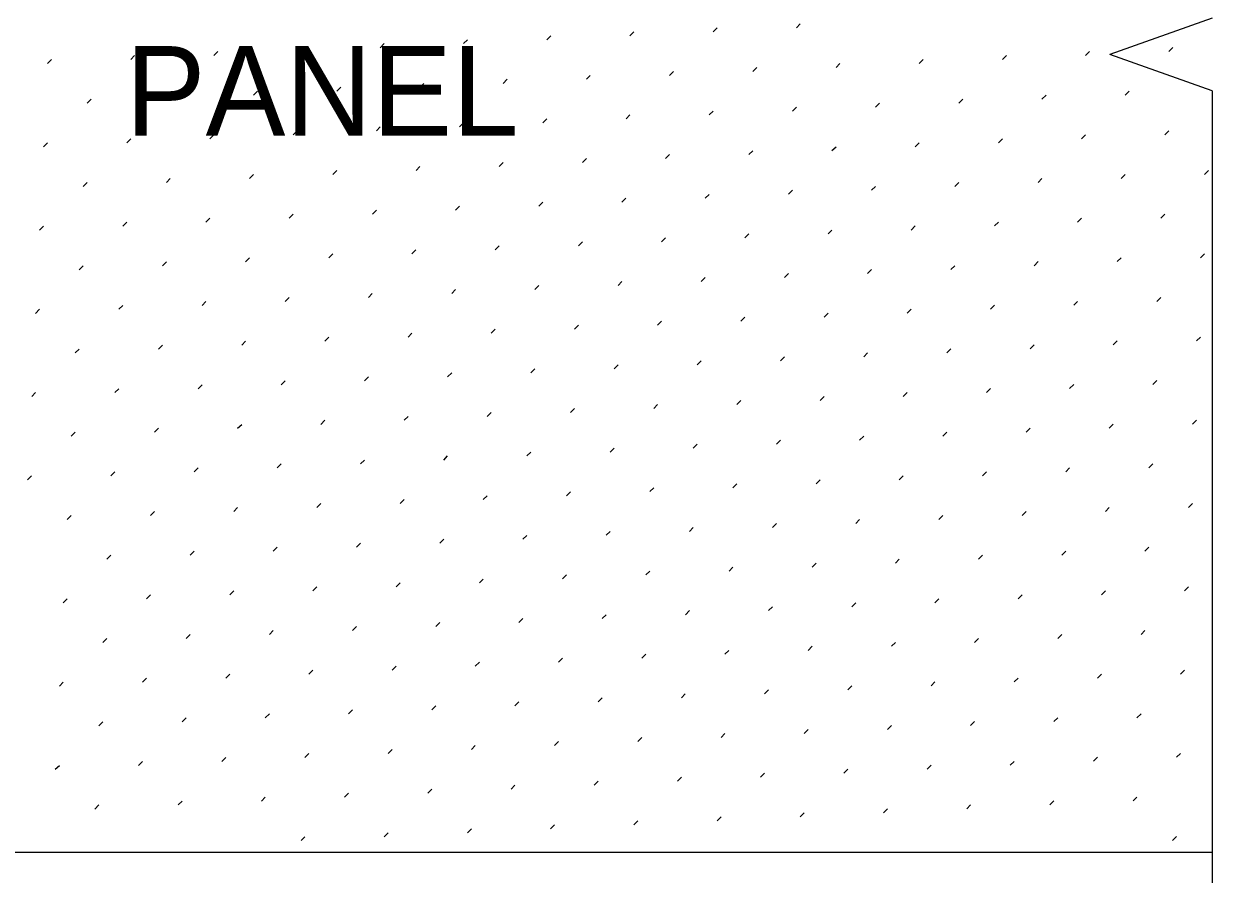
# Model space of a CAD drawing. Extents: x 49991.4 to 50021, y 49987.6 to 50011.4.
# Drawn here: x 50014.07 to 50015.13, y 49996.272 to 49997.03 of the extents above; entities that cross this region are included whole.
import ezdxf

# ---------------------------------------------------------------- set-up
doc = ezdxf.new("R2010")
doc.units = 0
for name, color, linetype in [('Level 1', 7, 'Continuous'), ('Level 10', 7, 'Continuous'), ('Level 2', 7, 'Continuous'), ('Level 6', 7, 'Continuous')]:
    doc.layers.add(name, color=color, linetype=linetype)

msp = doc.modelspace()

# ---------------------------------------------------------------- linework, layer by layer
at = {"layer": 'Level 1'}
msp.add_line((50013.9348, 49996.2915), (50015.1301, 49996.2915), dxfattribs=at)
at = {"layer": 'Level 10'}
for p, q in [((50014.6105, 49997.0196), (50014.614, 49997.0231)), ((50014.6848, 49997.0231), (50014.6883, 49997.0267)), ((50014.759, 49997.0267), (50014.7625, 49997.0302)), ((50014.3877, 49997.0089), (50014.3913, 49997.0125)), ((50014.462, 49997.0125), (50014.4655, 49997.016)), ((50014.5362, 49997.016), (50014.5398, 49997.0196)), ((50014.165, 49996.9983), (50014.1685, 49997.0019)), ((50014.2392, 49997.0019), (50014.2428, 49997.0054)), ((50014.3135, 49997.0054), (50014.317, 49997.0089)), ((50014.9429, 49996.9984), (50014.9464, 49997.0019)), ((50015.0171, 49997.0019), (50015.0207, 49997.0055)), ((50015.0914, 49997.0055), (50015.0949, 49997.009)), ((50014.0907, 49996.9948), (50014.0943, 49996.9983)), ((50014.7201, 49996.9878), (50014.7236, 49996.9913)), ((50014.7944, 49996.9913), (50014.7979, 49996.9948)), ((50014.8686, 49996.9948), (50014.8721, 49996.9984)), ((50014.4973, 49996.9771), (50014.5009, 49996.9807)), ((50014.5716, 49996.9807), (50014.5751, 49996.9842)), ((50014.6459, 49996.9842), (50014.6494, 49996.9878)), ((50014.2746, 49996.9665), (50014.2781, 49996.97)), ((50014.3488, 49996.97), (50014.3524, 49996.9736)), ((50014.4231, 49996.9736), (50014.4266, 49996.9771)), ((50015.0525, 49996.9666), (50015.056, 49996.9701)), ((50014.1261, 49996.9594), (50014.1296, 49996.963)), ((50014.2003, 49996.963), (50014.2039, 49996.9665)), ((50014.8297, 49996.9559), (50014.8333, 49996.9595)), ((50014.904, 49996.9595), (50014.9075, 49996.963)), ((50014.9782, 49996.963), (50014.9818, 49996.9666)), ((50014.607, 49996.9453), (50014.6105, 49996.9489)), ((50014.6812, 49996.9489), (50014.6847, 49996.9524)), ((50014.7555, 49996.9524), (50014.759, 49996.9559)), ((50014.3842, 49996.9347), (50014.3877, 49996.9382)), ((50014.4584, 49996.9382), (50014.462, 49996.9418)), ((50014.5327, 49996.9418), (50014.5362, 49996.9453)), ((50014.1614, 49996.9241), (50014.165, 49996.9276)), ((50014.2357, 49996.9276), (50014.2392, 49996.9311)), ((50014.3099, 49996.9312), (50014.3135, 49996.9347)), ((50014.9393, 49996.9241), (50014.9429, 49996.9277)), ((50015.0136, 49996.9277), (50015.0171, 49996.9312)), ((50015.0878, 49996.9312), (50015.0914, 49996.9348)), ((50014.0872, 49996.9205), (50014.0907, 49996.9241)), ((50014.7166, 49996.9135), (50014.7201, 49996.917)), ((50014.7908, 49996.9171), (50014.7944, 49996.9206)), ((50014.8651, 49996.9206), (50014.8686, 49996.9241)), ((50014.4938, 49996.9029), (50014.4973, 49996.9064)), ((50014.5681, 49996.9064), (50014.5716, 49996.91)), ((50014.6423, 49996.91), (50014.6458, 49996.9135)), ((50014.271, 49996.8923), (50014.2746, 49996.8958)), ((50014.3453, 49996.8958), (50014.3488, 49996.8993)), ((50014.4196, 49996.8993), (50014.4231, 49996.9029)), ((50015.0489, 49996.8923), (50015.0525, 49996.8959)), ((50015.1232, 49996.8959), (50015.1267, 49996.8994)), ((50014.1225, 49996.8852), (50014.1261, 49996.8887)), ((50014.1968, 49996.8887), (50014.2003, 49996.8922)), ((50014.8262, 49996.8817), (50014.8297, 49996.8852)), ((50014.9004, 49996.8852), (50014.904, 49996.8888)), ((50014.9747, 49996.8888), (50014.9782, 49996.8923)), ((50014.6034, 49996.8711), (50014.6069, 49996.8746)), ((50014.6777, 49996.8746), (50014.6812, 49996.8781)), ((50014.7519, 49996.8782), (50014.7555, 49996.8817)), ((50014.3807, 49996.8604), (50014.3842, 49996.864)), ((50014.4549, 49996.864), (50014.4584, 49996.8675)), ((50014.5292, 49996.8675), (50014.5327, 49996.8711)), ((50014.1579, 49996.8498), (50014.1614, 49996.8533)), ((50014.2321, 49996.8534), (50014.2357, 49996.8569)), ((50014.3064, 49996.8569), (50014.3099, 49996.8604)), ((50014.9358, 49996.8499), (50014.9393, 49996.8534)), ((50015.01, 49996.8534), (50015.0136, 49996.857)), ((50015.0843, 49996.857), (50015.0878, 49996.8605)), ((50014.0836, 49996.8463), (50014.0872, 49996.8498)), ((50014.713, 49996.8393), (50014.7166, 49996.8428)), ((50014.7873, 49996.8428), (50014.7908, 49996.8463)), ((50014.8615, 49996.8463), (50014.8651, 49996.8499)), ((50014.4903, 49996.8286), (50014.4938, 49996.8322)), ((50014.5645, 49996.8322), (50014.5681, 49996.8357)), ((50014.6388, 49996.8357), (50014.6423, 49996.8392)), ((50014.2675, 49996.818), (50014.271, 49996.8215)), ((50014.3418, 49996.8215), (50014.3453, 49996.8251)), ((50014.416, 49996.8251), (50014.4195, 49996.8286)), ((50015.0454, 49996.8181), (50015.0489, 49996.8216)), ((50015.1196, 49996.8216), (50015.1232, 49996.8251)), ((50014.119, 49996.8109), (50014.1225, 49996.8144)), ((50014.1932, 49996.8145), (50014.1968, 49996.818)), ((50014.8226, 49996.8074), (50014.8262, 49996.811)), ((50014.8969, 49996.811), (50014.9004, 49996.8145)), ((50014.9711, 49996.8145), (50014.9747, 49996.8181)), ((50014.5999, 49996.7968), (50014.6034, 49996.8003)), ((50014.6741, 49996.8004), (50014.6777, 49996.8039)), ((50014.7484, 49996.8039), (50014.7519, 49996.8074)), ((50014.3771, 49996.7862), (50014.3806, 49996.7897)), ((50014.4514, 49996.7897), (50014.4549, 49996.7933)), ((50014.5256, 49996.7933), (50014.5292, 49996.7968)), ((50014.1544, 49996.7756), (50014.1579, 49996.7791)), ((50014.2286, 49996.7791), (50014.2321, 49996.7826)), ((50014.3029, 49996.7826), (50014.3064, 49996.7862)), ((50014.9322, 49996.7756), (50014.9358, 49996.7792)), ((50015.0065, 49996.7792), (50015.01, 49996.7827)), ((50015.0807, 49996.7827), (50015.0843, 49996.7862)), ((50014.0801, 49996.772), (50014.0836, 49996.7756)), ((50014.7095, 49996.765), (50014.713, 49996.7685)), ((50014.7837, 49996.7685), (50014.7873, 49996.7721)), ((50014.858, 49996.7721), (50014.8615, 49996.7756)), ((50014.4867, 49996.7544), (50014.4903, 49996.7579)), ((50014.561, 49996.7579), (50014.5645, 49996.7615)), ((50014.6352, 49996.7615), (50014.6388, 49996.765)), ((50014.264, 49996.7437), (50014.2675, 49996.7473)), ((50014.3382, 49996.7473), (50014.3417, 49996.7508)), ((50014.4125, 49996.7508), (50014.416, 49996.7544)), ((50015.0418, 49996.7438), (50015.0454, 49996.7474)), ((50015.1161, 49996.7474), (50015.1196, 49996.7509)), ((50014.1155, 49996.7367), (50014.119, 49996.7402)), ((50014.1897, 49996.7402), (50014.1932, 49996.7437)), ((50014.8191, 49996.7332), (50014.8226, 49996.7367)), ((50014.8933, 49996.7367), (50014.8969, 49996.7403)), ((50014.9676, 49996.7403), (50014.9711, 49996.7438)), ((50014.5963, 49996.7226), (50014.5999, 49996.7261)), ((50014.6706, 49996.7261), (50014.6741, 49996.7296)), ((50014.7448, 49996.7296), (50014.7484, 49996.7332)), ((50014.3736, 49996.7119), (50014.3771, 49996.7155)), ((50014.4478, 49996.7155), (50014.4514, 49996.719)), ((50014.5221, 49996.719), (50014.5256, 49996.7226)), ((50014.1508, 49996.7013), (50014.1543, 49996.7048)), ((50014.2251, 49996.7048), (50014.2286, 49996.7084)), ((50014.2993, 49996.7084), (50014.3028, 49996.7119)), ((50014.9287, 49996.7014), (50014.9322, 49996.7049)), ((50015.0029, 49996.7049), (50015.0065, 49996.7085)), ((50015.0772, 49996.7085), (50015.0807, 49996.712)), ((50014.0766, 49996.6978), (50014.0801, 49996.7013)), ((50014.7059, 49996.6907), (50014.7095, 49996.6943)), ((50014.7802, 49996.6943), (50014.7837, 49996.6978)), ((50014.8544, 49996.6978), (50014.858, 49996.7014)), ((50014.4832, 49996.6801), (50014.4867, 49996.6837)), ((50014.5574, 49996.6837), (50014.561, 49996.6872)), ((50014.6317, 49996.6872), (50014.6352, 49996.6907)), ((50014.2604, 49996.6695), (50014.264, 49996.673)), ((50014.3347, 49996.673), (50014.3382, 49996.6766)), ((50014.4089, 49996.6766), (50014.4125, 49996.6801)), ((50015.0383, 49996.6696), (50015.0418, 49996.6731)), ((50015.1126, 49996.6731), (50015.1161, 49996.6766)), ((50014.1119, 49996.6624), (50014.1154, 49996.6659)), ((50014.1862, 49996.6659), (50014.1897, 49996.6695)), ((50014.8155, 49996.6589), (50014.8191, 49996.6625)), ((50014.8898, 49996.6625), (50014.8933, 49996.666)), ((50014.9641, 49996.666), (50014.9676, 49996.6696)), ((50014.5928, 49996.6483), (50014.5963, 49996.6518)), ((50014.667, 49996.6519), (50014.6706, 49996.6554)), ((50014.7413, 49996.6554), (50014.7448, 49996.6589)), ((50014.37, 49996.6377), (50014.3736, 49996.6412)), ((50014.4443, 49996.6412), (50014.4478, 49996.6448)), ((50014.5185, 49996.6448), (50014.5221, 49996.6483)), ((50014.1473, 49996.6271), (50014.1508, 49996.6306)), ((50014.2215, 49996.6306), (50014.2251, 49996.6341)), ((50014.2958, 49996.6341), (50014.2993, 49996.6377)), ((50014.9252, 49996.6271), (50014.9287, 49996.6307)), ((50014.9994, 49996.6307), (50015.0029, 49996.6342)), ((50015.0737, 49996.6342), (50015.0772, 49996.6377)), ((50014.073, 49996.6235), (50014.0765, 49996.627)), ((50014.7024, 49996.6165), (50014.7059, 49996.62)), ((50014.7766, 49996.62), (50014.7802, 49996.6236)), ((50014.8509, 49996.6236), (50014.8544, 49996.6271)), ((50014.4796, 49996.6059), (50014.4832, 49996.6094)), ((50014.5539, 49996.6094), (50014.5574, 49996.6129)), ((50014.6281, 49996.613), (50014.6317, 49996.6165)), ((50014.2569, 49996.5952), (50014.2604, 49996.5988)), ((50014.3311, 49996.5988), (50014.3347, 49996.6023)), ((50014.4054, 49996.6023), (50014.4089, 49996.6059)), ((50015.0348, 49996.5953), (50015.0383, 49996.5988)), ((50015.109, 49996.5989), (50015.1126, 49996.6024)), ((50014.1084, 49996.5882), (50014.1119, 49996.5917)), ((50014.1826, 49996.5917), (50014.1862, 49996.5952)), ((50014.812, 49996.5847), (50014.8155, 49996.5882)), ((50014.8863, 49996.5882), (50014.8898, 49996.5918)), ((50014.9605, 49996.5918), (50014.964, 49996.5953)), ((50014.5892, 49996.5741), (50014.5928, 49996.5776)), ((50014.6635, 49996.5776), (50014.667, 49996.5811)), ((50014.7377, 49996.5811), (50014.7413, 49996.5847)), ((50014.3665, 49996.5634), (50014.37, 49996.567)), ((50014.4407, 49996.567), (50014.4443, 49996.5705)), ((50014.515, 49996.5705), (50014.5185, 49996.574)), ((50014.1437, 49996.5528), (50014.1473, 49996.5563)), ((50014.218, 49996.5563), (50014.2215, 49996.5599)), ((50014.2922, 49996.5599), (50014.2958, 49996.5634)), ((50014.9216, 49996.5529), (50014.9251, 49996.5564)), ((50014.9959, 49996.5564), (50014.9994, 49996.5599)), ((50015.0701, 49996.56), (50015.0737, 49996.5635)), ((50014.6989, 49996.5422), (50014.7024, 49996.5458)), ((50014.7731, 49996.5458), (50014.7766, 49996.5493)), ((50014.8474, 49996.5493), (50014.8509, 49996.5529)), ((50014.4761, 49996.5316), (50014.4796, 49996.5351)), ((50014.5503, 49996.5352), (50014.5539, 49996.5387)), ((50014.6246, 49996.5387), (50014.6281, 49996.5422)), ((50014.2533, 49996.521), (50014.2569, 49996.5245)), ((50014.3276, 49996.5245), (50014.3311, 49996.5281)), ((50014.4018, 49996.5281), (50014.4054, 49996.5316)), ((50015.0312, 49996.5211), (50015.0348, 49996.5246)), ((50015.1055, 49996.5246), (50015.109, 49996.5281)), ((50014.1048, 49996.5139), (50014.1084, 49996.5174)), ((50014.1791, 49996.5174), (50014.1826, 49996.521)), ((50014.8085, 49996.5104), (50014.812, 49996.514)), ((50014.8827, 49996.514), (50014.8862, 49996.5175)), ((50014.957, 49996.5175), (50014.9605, 49996.521)), ((50014.5857, 49996.4998), (50014.5892, 49996.5033)), ((50014.66, 49996.5033), (50014.6635, 49996.5069)), ((50014.7342, 49996.5069), (50014.7377, 49996.5104)), ((50014.3629, 49996.4892), (50014.3665, 49996.4927)), ((50014.4372, 49996.4927), (50014.4407, 49996.4963)), ((50014.5114, 49996.4963), (50014.515, 49996.4998)), ((50014.1402, 49996.4785), (50014.1437, 49996.4821)), ((50014.2144, 49996.4821), (50014.218, 49996.4856)), ((50014.2887, 49996.4856), (50014.2922, 49996.4892)), ((50014.9181, 49996.4786), (50014.9216, 49996.4822)), ((50014.9923, 49996.4822), (50014.9959, 49996.4857)), ((50015.0666, 49996.4857), (50015.0701, 49996.4892)), ((50014.6953, 49996.468), (50014.6988, 49996.4715)), ((50014.7696, 49996.4715), (50014.7731, 49996.4751)), ((50014.8438, 49996.4751), (50014.8474, 49996.4786)), ((50014.4725, 49996.4574), (50014.4761, 49996.4609)), ((50014.5468, 49996.4609), (50014.5503, 49996.4644)), ((50014.6211, 49996.4644), (50014.6246, 49996.468)), ((50014.2498, 49996.4467), (50014.2533, 49996.4503)), ((50014.324, 49996.4503), (50014.3276, 49996.4538)), ((50014.3983, 49996.4538), (50014.4018, 49996.4574)), ((50015.0277, 49996.4468), (50015.0312, 49996.4503)), ((50015.1019, 49996.4503), (50015.1055, 49996.4539)), ((50014.1013, 49996.4396), (50014.1048, 49996.4432)), ((50014.1755, 49996.4432), (50014.1791, 49996.4467)), ((50014.8049, 49996.4362), (50014.8085, 49996.4397)), ((50014.8792, 49996.4397), (50014.8827, 49996.4433)), ((50014.9534, 49996.4433), (50014.957, 49996.4468)), ((50014.5822, 49996.4255), (50014.5857, 49996.4291)), ((50014.6564, 49996.4291), (50014.6599, 49996.4326)), ((50014.7307, 49996.4326), (50014.7342, 49996.4362)), ((50014.3594, 49996.4149), (50014.3629, 49996.4185)), ((50014.4337, 49996.4185), (50014.4372, 49996.422)), ((50014.5079, 49996.422), (50014.5114, 49996.4255)), ((50014.1366, 49996.4043), (50014.1402, 49996.4078)), ((50014.2109, 49996.4078), (50014.2144, 49996.4114)), ((50014.2851, 49996.4114), (50014.2887, 49996.4149)), ((50014.9145, 49996.4044), (50014.9181, 49996.4079)), ((50014.9888, 49996.4079), (50014.9923, 49996.4114)), ((50015.063, 49996.4114), (50015.0666, 49996.415)), ((50014.6918, 49996.3937), (50014.6953, 49996.3973)), ((50014.766, 49996.3973), (50014.7696, 49996.4008)), ((50014.8403, 49996.4008), (50014.8438, 49996.4044)), ((50014.469, 49996.3831), (50014.4725, 49996.3866)), ((50014.5433, 49996.3866), (50014.5468, 49996.3902)), ((50014.6175, 49996.3902), (50014.621, 49996.3937)), ((50014.2462, 49996.3725), (50014.2498, 49996.376)), ((50014.3205, 49996.376), (50014.324, 49996.3796)), ((50014.3948, 49996.3796), (50014.3983, 49996.3831)), ((50015.0241, 49996.3726), (50015.0277, 49996.3761)), ((50015.0984, 49996.3761), (50015.1019, 49996.3796)), ((50014.0977, 49996.3654), (50014.1013, 49996.3689)), ((50014.172, 49996.3689), (50014.1755, 49996.3725)), ((50014.8014, 49996.3619), (50014.8049, 49996.3655)), ((50014.8756, 49996.3655), (50014.8792, 49996.369)), ((50014.9499, 49996.369), (50014.9534, 49996.3725)), ((50014.5786, 49996.3513), (50014.5822, 49996.3548)), ((50014.6529, 49996.3548), (50014.6564, 49996.3584)), ((50014.7271, 49996.3584), (50014.7307, 49996.3619)), ((50014.3559, 49996.3407), (50014.3594, 49996.3442)), ((50014.4301, 49996.3442), (50014.4336, 49996.3477)), ((50014.5044, 49996.3478), (50014.5079, 49996.3513)), ((50014.1331, 49996.33), (50014.1366, 49996.3336)), ((50014.2073, 49996.3336), (50014.2109, 49996.3371)), ((50014.2816, 49996.3371), (50014.2851, 49996.3407)), ((50014.911, 49996.3301), (50014.9145, 49996.3336)), ((50014.9852, 49996.3337), (50014.9888, 49996.3372)), ((50015.0595, 49996.3372), (50015.063, 49996.3407)), ((50014.6882, 49996.3195), (50014.6918, 49996.323)), ((50014.7625, 49996.323), (50014.766, 49996.3266)), ((50014.8367, 49996.3266), (50014.8403, 49996.3301)), ((50014.4655, 49996.3089), (50014.469, 49996.3124)), ((50014.5397, 49996.3124), (50014.5433, 49996.3159)), ((50014.614, 49996.3159), (50014.6175, 49996.3195)), ((50014.317, 49996.3018), (50014.3205, 49996.3053)), ((50014.3912, 49996.3053), (50014.3947, 49996.3088)), ((50015.0948, 49996.3018), (50015.0984, 49996.3054))]:
    msp.add_line(p, q, dxfattribs=at)
at = {"layer": 'Level 6'}
for p, q in [((50015.1301, 49997.0352), (50015.0387, 49997.0028)), ((50015.1301, 49996.9704), (50015.0387, 49997.0028)), ((50015.1301, 49996.9704), (50015.1301, 49995.6))]:
    msp.add_line(p, q, dxfattribs=at)

# ---------------------------------------------------------------- texts
at = {"layer": 'Level 2'}
msp.add_text('PANEL', height=0.08, dxfattribs=at).set_placement((50014.1604, 49996.9303))

doc.saveas('drawing.dxf')
